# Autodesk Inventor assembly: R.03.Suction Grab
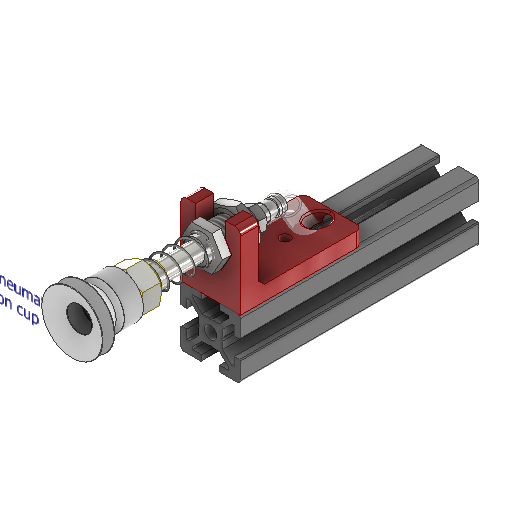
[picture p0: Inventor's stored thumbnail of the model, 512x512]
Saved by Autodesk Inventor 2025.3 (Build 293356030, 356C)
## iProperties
Created: 2021-02
Part Number: R.03.Suction Grab
Document SubType Name: Assembly
Designer: Михальчик
Author: Михальчик
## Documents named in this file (11)
- C:\Users\R5800u\Desktop\antropomorfo_nema6\ventosa\ventosa_20mm.iam
- C:\Users\R5800u\Desktop\antropomorfo_nema6\ventosa\R.03.01.Cup.ipt
- C:\Users\R5800u\Desktop\antropomorfo_nema6\ventosa\R.03.02.Tube.ipt
- C:\Users\R5800u\Desktop\antropomorfo_nema6\ventosa\Compress Spring11.ipt
- C:\Users\R5800u\Desktop\antropomorfo_nema6\ventosa\R.03.04.Fitting.ipt
- C:\Users\R5800u\Desktop\antropomorfo_nema6\ventosa\DIN 3771 - 5 x 1,8 - N - NBR 70(2).ipt
- C:\Users\R5800u\Desktop\antropomorfo_nema6\ventosa\R.03.05.Interface.ipt
- C:\Users\R5800u\Desktop\antropomorfo_nema6\ventosa\R.03.06.Nut.ipt
- C:\Users\R5800u\Desktop\antropomorfo_nema6\ventosa\blocco_ventosa_profilato.ipt
- C:\Users\R5800u\Desktop\antropomorfo_nema6\ventosa\tubo_silicone.ipt
- C:\Users\R5800u\Desktop\antropomorfo_nema6\tslot-20x20-100mm.ipt
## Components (10 placed, 10 different names)
1. R.03.01.Cup:1 — Mate:1, Mate:2
2. R.03.02.Tube:1 — Mate:1, Mate:2, Mate:3, Flush:1, Mate:4, Mate:6, Rigido:1
3. R.03.03.Spring:1 — Mate:3, Flush:1, Mate:7
4. R.03.04.Fitting:1 — Mate:4, Rigido:1, Allineato:4
5. DIN 3771 - 5 x 1,8 - N - NBR 70(2):1 — Rotazionale:1
6. R.03.05.Interface:1 — Mate:6, Mate:7, Mate:8, Rotazionale:1, Rotazionale:2, Angolo:2
7. R.03.06.Nut:1 — Mate:8, Coincidente:9
8. blocco_ventosa_profilato:1 — Coincidente:9, Angolo:1, Coincidente:10, Allineato:2, Allineato:3, Rotazionale:2, Angolo:2
9. tslot-20x20-100mm:1 — Coincidente:10, Allineato:2, Allineato:3
10. tubo_silicone:1 — Allineato:4
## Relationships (18: Mate 9, Flush 4, RevoluteJoint 2, Angle 2, WeldJoint 1)
- Mate:1: R.03.01.Cup:1 ↔ R.03.02.Tube:1
- Mate:2: R.03.01.Cup:1 ↔ R.03.02.Tube:1
- Mate:3: R.03.02.Tube:1 ↔ R.03.03.Spring:1
- Flush:1: R.03.02.Tube:1 ↔ R.03.03.Spring:1
- Mate:4: R.03.02.Tube:1 ↔ R.03.04.Fitting:1
- Mate:6: R.03.02.Tube:1 ↔ R.03.05.Interface:1
- Mate:7: R.03.03.Spring:1 ↔ R.03.05.Interface:1
- Mate:8: R.03.05.Interface:1 ↔ R.03.06.Nut:1
- Rotazionale:1 [RevoluteJoint]: DIN 3771 - 5 x 1,8 - N - NBR 70(2):1 ↔ R.03.05.Interface:1
- Rigido:1 [WeldJoint]: R.03.02.Tube:1 ↔ R.03.04.Fitting:1
- Coincidente:9 [Mate]: R.03.06.Nut:1 ↔ blocco_ventosa_profilato:1
- Angolo:1 [Angle]: blocco_ventosa_profilato:1
- Coincidente:10 [Mate]: blocco_ventosa_profilato:1 ↔ tslot-20x20-100mm:1
- Allineato:2 [Flush]: blocco_ventosa_profilato:1 ↔ tslot-20x20-100mm:1
- Allineato:3 [Flush]: blocco_ventosa_profilato:1 ↔ tslot-20x20-100mm:1
- Allineato:4 [Flush]: R.03.04.Fitting:1 ↔ tubo_silicone:1
- Rotazionale:2 [RevoluteJoint]: R.03.05.Interface:1 ↔ blocco_ventosa_profilato:1
- Angolo:2 [Angle]: R.03.05.Interface:1 ↔ blocco_ventosa_profilato:1
